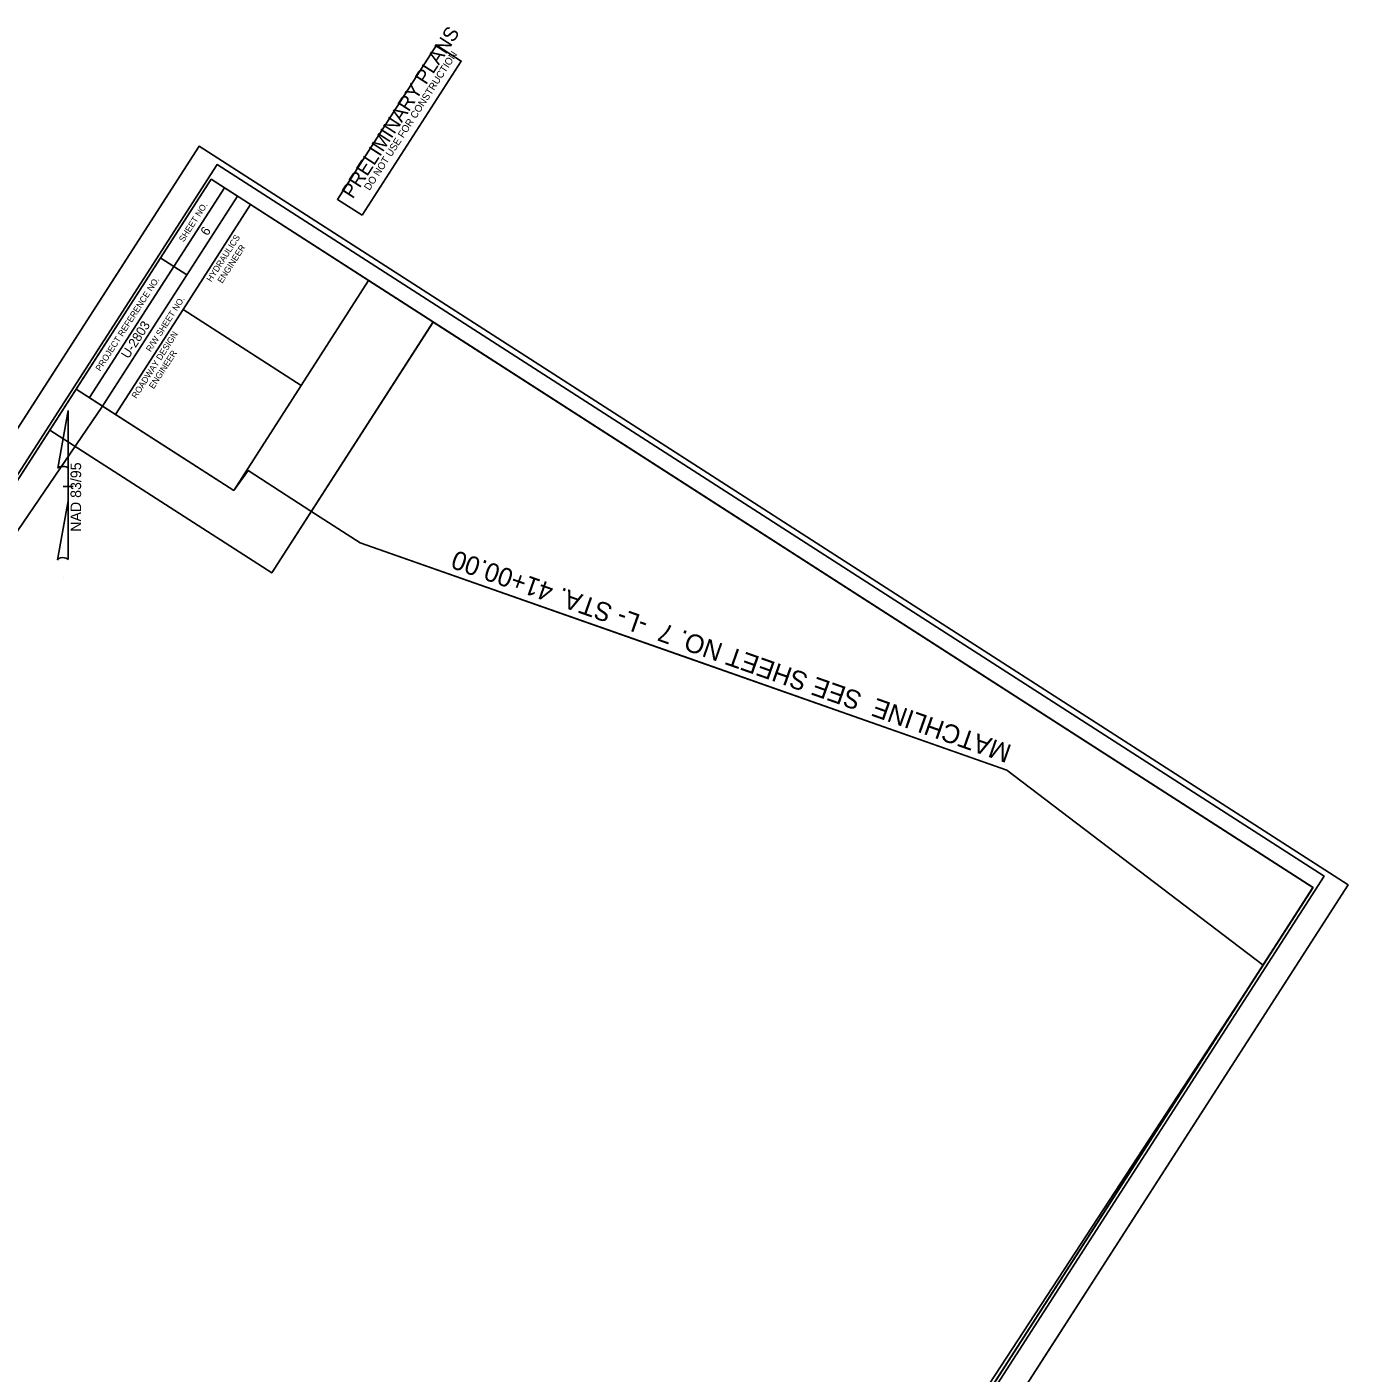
# Model space of a CAD drawing. Extents: x 1976127 to 1977958, y 779377 to 781490.
# Drawn here: x 1976899 to 1977958, y 780410 to 781490 of the extents above; entities that cross this region are included whole.
import ezdxf

# ---------------------------------------------------------------- set-up
doc = ezdxf.new("R2010")
doc.units = 0
for name, color, linetype in [('Matchline', 7, 'Continuous'), ('Matchline Text', 7, 'Continuous'), ('Old_Level_1', 7, 'Continuous'), ('Sheet Clip Boundary CELL', 7, 'Continuous'), ('Sheet Cutting Line CELL', 7, 'Continuous'), ('Sheet Data Field CELL', 7, 'Continuous'), ('Sheet North Arrow Point CELL', 7, 'Continuous'), ('Sheet Plan CELL', 7, 'Continuous'), ('Sheet Plan Layout CELL', 7, 'Continuous'), ('Sheet Plot Border Inside CELL', 7, 'Continuous'), ('Sheet Plot Border Outside CELL', 7, 'Continuous'), ('Sheet Sticker Preliminary CELL', 7, 'Continuous')]:
    doc.layers.add(name, color=color, linetype=linetype)

msp = doc.modelspace()

# ---------------------------------------------------------------- linework, layer by layer
at = {"layer": 'Matchline'}
msp.add_lwpolyline([(1977684.7, 780893.8), (1977425.2, 780985), (1977166.5, 781076)], dxfattribs=at)
at = {"layer": 'Old_Level_1'}
for p, q in [((1976924, 781135.9), (1976932.2, 781182.2)), ((1976932.3, 781182.2), (1976932.2, 781182.2)), ((1976932.3, 781182.2), (1976932.2, 781182.2)), ((1976932.3, 781182.2), (1976932.2, 781134.4)), ((1976932.2, 781109.6), (1976932.2, 781135.8)), ((1976932.2, 781134.4), (1976932.2, 781135.8)), ((1976931.8, 781121.2), (1976928.2, 781121.2)), ((1976928.2, 781121.2), (1976928.2, 781121.2)), ((1976928.3, 781121.2), (1976936.3, 781121.2)), ((1976932.2, 781109.6), (1976923.8, 781062.4)), ((1976932.2, 781062.6), (1976932.2, 781109.6))]:
    msp.add_line(p, q, dxfattribs=at)
for centre, start_param, end_param in [((1976928.1, 781135.4), 0.216388, 2.908219), ((1976928.1, 781062.2), 0.201328, 3.141593)]:
    msp.add_ellipse(centre, major_axis=(4.23, -0.03), ratio=0.461098, start_param=start_param, end_param=end_param, dxfattribs=at)
at = {"layer": 'Sheet Clip Boundary CELL'}
msp.add_lwpolyline([(1977101.1, 779831), (1977215.7, 780009.2), (1977355.5, 779919.3), (1977890.2, 780737.4), (1977684.7, 780893.8), (1977248.3, 781047.2), (1977166.5, 781076), (1977126.8, 781101.5), (1977076.7, 781133.9), (1977065, 781118.1), (1976959.9, 781185.7), (1976680, 780774.9), (1976779.9, 780758.8), (1976666.1, 780754.4), (1976646, 780725), (1976307, 780212.9), (1976557, 780088.2), (1976950.5, 779704.7)], close=True, dxfattribs=at)
at = {"layer": 'Sheet Cutting Line CELL'}
for p, q in [((1977037.3, 781394), (1976126.7, 779978)), ((1977047.7, 779385.8), (1977958.3, 780801.7))]:
    msp.add_line(p, q, dxfattribs=at)
at = {"layer": 'Sheet North Arrow Point CELL'}
msp.add_line((1976928.6, 781048.6), (1976928.6, 781048.6), dxfattribs=at)
at = {"layer": 'Sheet Plan CELL'}
for p, q in [((1976949.3, 781192.5), (1977057.6, 781360.7)), ((1976959.9, 781185.7), (1977068.1, 781354)), ((1976959.9, 781185.7), (1977068.1, 781354)), ((1977006.5, 781304.4), (1977027.5, 781290.9)), ((1977024.5, 781263.1), (1977119.1, 781202.3)), ((1976959.9, 781185.7), (1976970.4, 781179))]:
    msp.add_line(p, q, dxfattribs=at)
for points in [[(1977047, 781367.6), (1976235.7, 780105.9), (1977118.8, 779538), (1977930.2, 780799.6)], [(1976938.8, 781199.3), (1977047, 781367.6), (1977068.1, 781354), (1976959.9, 781185.7)], [(1977024.5, 781263.1), (1977078.6, 781347.2), (1977173.2, 781286.4), (1977119.1, 781202.3)], [(1977118.8, 779538), (1976235.7, 780105.9), (1976938.8, 781199.3), (1977065, 781118.1), (1977173.2, 781286.4), (1977930.2, 780799.6)], [(1976970.4, 781179), (1977024.5, 781263.1), (1977119.1, 781202.3), (1977065, 781118.1)]]:
    msp.add_lwpolyline(points, close=True, dxfattribs=at)
at = {"layer": 'Sheet Plan Layout CELL'}
for points in [[(1977095.5, 781051.9), (1977224.9, 781253.2), (1977047, 781367.6), (1976917.6, 781166.3)], [(1976235.7, 780105.9), (1977118.8, 779538), (1977930.1, 780799.6), (1977224.9, 781253.1), (1977095.5, 781051.9), (1976917.6, 781166.3)]]:
    msp.add_lwpolyline(points, close=True, dxfattribs=at)
at = {"layer": 'Sheet Plot Border Inside CELL'}
msp.add_lwpolyline([(1977037.9, 779407.5), (1977939, 780808.8), (1977051.7, 781379.4), (1976150.5, 779978.2)], close=True, dxfattribs=at)
at = {"layer": 'Sheet Plot Border Outside CELL'}
msp.add_lwpolyline([(1977047.7, 779385.8), (1977958.3, 780801.7), (1977037.3, 781394), (1976126.7, 779978)], close=True, dxfattribs=at)
at = {"layer": 'Sheet Sticker Preliminary CELL'}
msp.add_lwpolyline([(1977167.9, 781338.7), (1977148.2, 781351.4), (1977227.7, 781475), (1977247.4, 781462.3)], close=True, dxfattribs=at)

# ---------------------------------------------------------------- texts
at = {"layer": 'Matchline Text'}
msp.add_text('MATCHLINE  SEE SHEET NO. 7  -L- STA. 41+00.00', height=15, rotation=160.6265, dxfattribs=at).set_placement((1977689.5, 780913.4))
at = {"layer": 'Old_Level_1'}
msp.add_text('NAD 83/95', height=8.5, rotation=89.9647, dxfattribs=at).set_placement((1976942.7, 781084.9))
at = {"layer": 'Sheet Data Field CELL'}
for s, p in [('6', (1977044.1, 781321.7)), ('U-2803   ', (1976980.6, 781223.1))]:
    msp.add_text(s, height=7.5, rotation=57.255, dxfattribs=at).set_placement(p)
at = {"layer": 'Sheet Plan CELL'}
for s, p in [('SHEET NO.', (1977024.9, 781316.8)), ('HYDRAULICS', (1977047.1, 781284.8)), ('ENGINEER', (1977055.8, 781283.7)), ('PROJECT REFERENCE NO.', (1976958.1, 781213.2)), ('R/W SHEET NO.', (1976998.5, 781228.7)), ('ROADWAY DESIGN', (1976987, 781191.3)), ('ENGINEER', (1977000.9, 781199))]:
    msp.add_text(s, height=5, rotation=57.255, dxfattribs=at).set_placement(p)
at = {"layer": 'Sheet Sticker Preliminary CELL'}
for s, height, p in [('PRELIMINARY PLANS', 11.52, (1977160.4, 781351.3)), ('DO NOT USE FOR CONSTRUCTION', 5.76, (1977173.9, 781358.1))]:
    msp.add_text(s, height=height, rotation=57.255, dxfattribs=at).set_placement(p)

doc.saveas('drawing.dxf')
